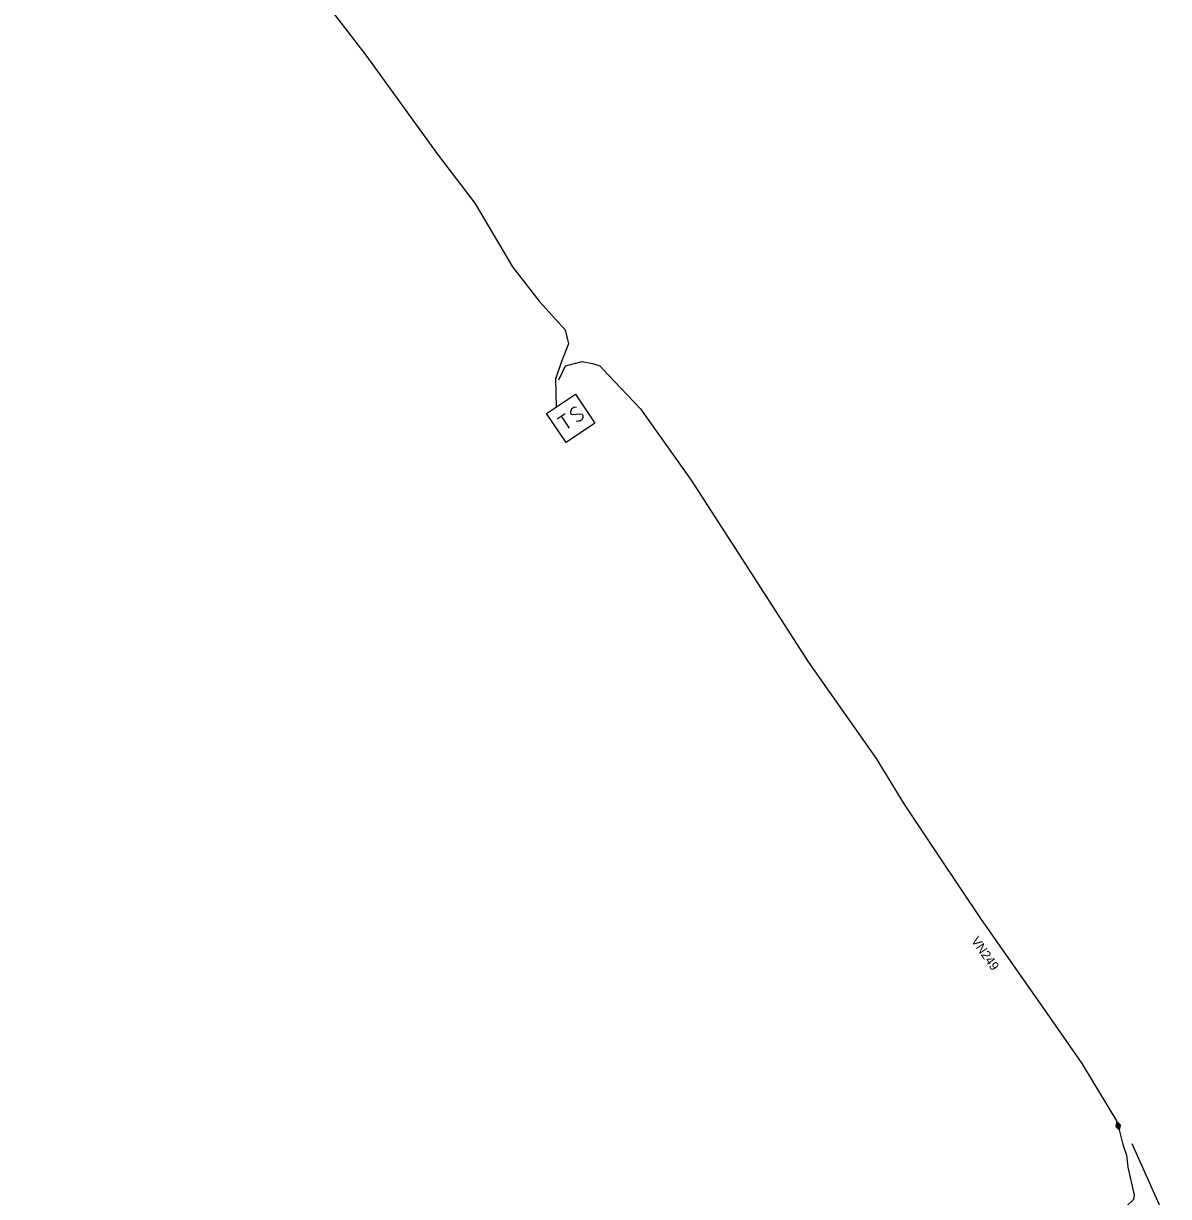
# Model space of a CAD drawing. Extents: x -643811 to -636362, y -1117362 to -1108614.
# Drawn here: x -640902 to -640777.9, y -1115802.7 to -1115675.5 of the extents above; entities that cross this region are included whole.
import ezdxf

# ---------------------------------------------------------------- set-up
doc = ezdxf.new("R2010")
doc.units = 0
for name, color, linetype in [('19', 7, 'Continuous'), ('25', 7, 'Continuous'), ('5', 7, 'Continuous'), ('7', 7, 'Continuous'), ('9', 7, 'Continuous')]:
    doc.layers.add(name, color=color, linetype=linetype)

# ---------------------------------------------------------------- blocks, each defined once
blk = doc.blocks.new('VN870')
at = {"layer": '19'}
for points in [[(0, -0.25), (0.5, 0), (0, 0.25), (-0.5, 0), (0, -0.25)], [(0.37, 0), (0, 0.19), (-0.36, 0), (0, -0.19), (0.37, 0)], [(0.24, 0), (0, 0.12), (-0.25, 0), (0, -0.12), (0.24, 0)], [(0.12, 0), (0, 0.06), (-0.13, 0), (0, -0.06), (0.12, 0)]]:
    blk.add_lwpolyline(points, dxfattribs=at)
blk = doc.blocks.new('VN640')
at = {"layer": '25'}
for points in [[(-1.89, 1.89), (1.89, 1.89)], [(-1.89, -1.89), (-1.89, 1.89)], [(1.89, 1.89), (1.89, -1.89)], [(-1.26, 0.79), (-0.22, 0.79)], [(-0.73, 0.79), (-0.73, -0.79)], [(1.2, 0.66), (0.94, 0.79), (0.66, 0.79), (0.41, 0.66), (0.28, 0.47), (0.28, 0.41), (0.41, 0.22), (1.13, -0.16), (1.26, -0.32), (1.26, -0.47), (1.13, -0.66), (0.91, -0.79), (0.63, -0.79), (0.5, -0.73), (0.28, -0.6)], [(1.89, -1.89), (-1.89, -1.89)]]:
    blk.add_lwpolyline(points, dxfattribs=at)

msp = doc.modelspace()

# ---------------------------------------------------------------- linework, layer by layer
at = {"layer": '5'}
for points in [[(-640873.21, -1115668.17), (-640864.94, -1115678.93), (-640857.07, -1115689.77), (-640853.12, -1115694.97), (-640849.03, -1115701.89), (-640846.13, -1115705.61), (-640843.33, -1115708.72), (-640842.96, -1115710.22), (-640843.71, -1115712.14), (-640844.36, -1115714.07), (-640844.28, -1115717.03)], [(-640844.01, -1115714.12), (-640843.29, -1115712.61), (-640841.49, -1115712.13), (-640840.35, -1115712.36), (-640839.55, -1115712.62), (-640838.65, -1115713.6), (-640835.15, -1115717.27), (-640829.68, -1115724.99), (-640822.76, -1115735.7), (-640816.97, -1115744.7), (-640809.62, -1115755.16), (-640806.55, -1115760.2), (-640802.78, -1115765.85), (-640798.24, -1115772.61), (-640791.38, -1115782.43), (-640787.33, -1115788.24), (-640783.55, -1115794.45), (-640783.38, -1115794.99)], [(-640783.38, -1115794.99), (-640782.87, -1115797), (-640782.49, -1115798.19), (-640782.33, -1115799.46), (-640781.64, -1115802.51), (-640781.73, -1115802.98), (-640782.54, -1115803.79), (-640788.49, -1115807.86), (-640789.31, -1115808), (-640792.61, -1115807.53), (-640794.06, -1115807.74), (-640807.33, -1115817.44), (-640811.23, -1115820.26), (-640840.35, -1115841.08), (-640868.48, -1115861.21), (-640889.72, -1115876.16), (-640898.02, -1115882.09), (-640900.44, -1115883.81), (-640902.03, -1115884.89)]]:
    msp.add_lwpolyline(points, dxfattribs=at)
at = {"layer": '9'}
msp.add_lwpolyline([(-640781.91, -1115796.89), (-640777.92, -1115805.79)], dxfattribs=at)

# ---------------------------------------------------------------- block references
at = {"layer": '19', "rotation": -72.00000000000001}
msp.add_blockref('VN870', (-640783.38, -1115794.99), dxfattribs=at)
at = {"layer": '25', "rotation": 34}
msp.add_blockref('VN640', (-640842.71, -1115718.3), dxfattribs=at)

# ---------------------------------------------------------------- texts
at = {"layer": '7'}
msp.add_text('VN249', height=0.994, rotation=304.963, dxfattribs=at).set_placement((-640799.36, -1115774.93))

doc.saveas('drawing.dxf')
